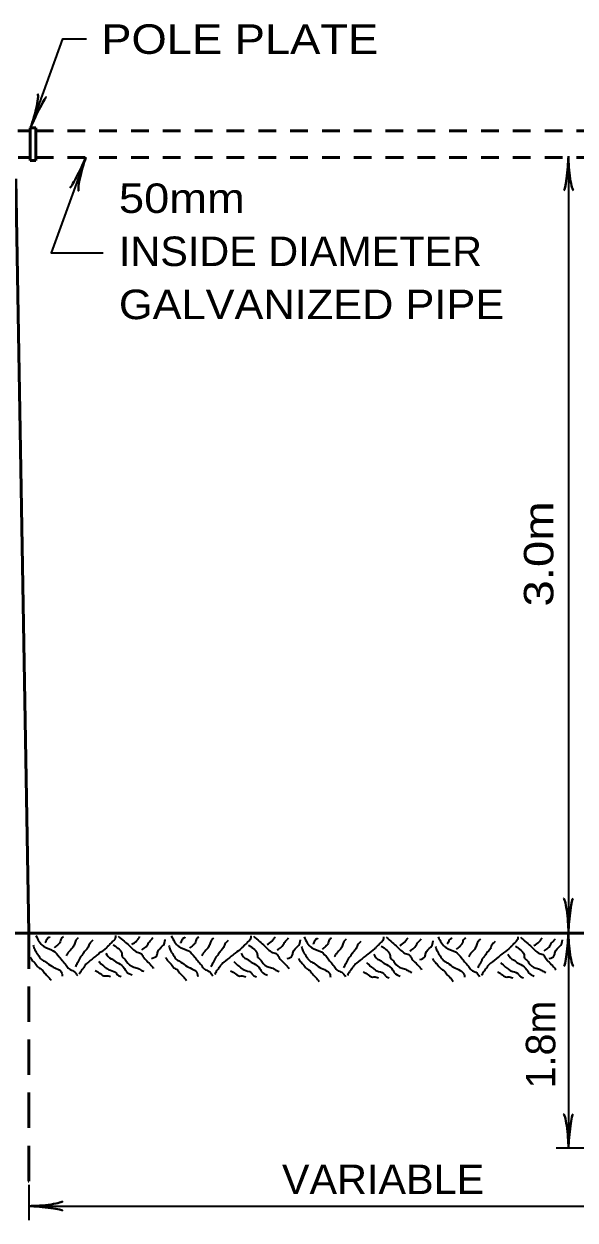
# Model space of a CAD drawing. Extents: x 14808 to 15663, y 10944 to 11488.
# Drawn here: x 15295.9 to 15352, y 11248.2 to 11369.9 of the extents above; entities that cross this region are included whole.
import ezdxf
from ezdxf.enums import TextEntityAlignment as Align

# ---------------------------------------------------------------- set-up
doc = ezdxf.new("R2010")
doc.units = 0
doc.header["$LTSCALE"] = 1.2
doc.linetypes.add('MEDIUM_DASHED', pattern=[4.5, 3, -1.5])
doc.linetypes.add('SHORT_DASHED', pattern=[2.7, 1.5, -1.2])
doc.layers.add('1', color=7, linetype='Continuous', lineweight=53)

msp = doc.modelspace()

# ---------------------------------------------------------------- linework, layer by layer
at = {"layer": '1'}
for p, q in [((15295.278, 11358.975), (15296.525, 11358.975)), ((15296.525, 11359.275), (15296.525, 11355.976)), ((15296.525, 11359.275), (15297.125, 11359.275)), ((15297.125, 11359.275), (15297.125, 11355.976)), ((15295.325, 11356.276), (15296.525, 11356.276)), ((15296.525, 11355.976), (15297.125, 11355.976)), ((15295.063, 11354.093), (15296.402, 11277.361)), ((15267.529, 11277.361), (15491.726, 11277.361))]:
    msp.add_line(p, q, dxfattribs=at)
at = {"layer": '1', "linetype": 'SHORT_DASHED'}
for p, q in [((15297.1, 11358.975), (15369.889, 11358.975)), ((15297.101, 11356.276), (15369.889, 11356.276))]:
    msp.add_line(p, q, dxfattribs=at)
at = {"layer": '1', "linetype": 'MEDIUM_DASHED'}
for p in [(15296.402, 11277.361), (15285.529, 11252.161)]:
    msp.add_line(p, (15296.402, 11252.161), dxfattribs=at)
at = {"layer": '1', "lineweight": 35}
for p, q in [((15373.088, 11255.52), (15350.104, 11255.52)), ((15296.404, 11251.793), (15296.404, 11248.194)), ((15296.404, 11249.616), (15373.132, 11249.616))]:
    msp.add_line(p, q, dxfattribs=at)
for points in [[(15296.595, 11359.332), (15299.878, 11368.353), (15302.278, 11368.353)], [(15302.201, 11356.276), (15298.672, 11346.579), (15303.978, 11346.579)], [(15351.358, 11356.377), (15351.358, 11277.463), (15351.358, 11255.52)]]:
    msp.add_lwpolyline(points, dxfattribs=at)
at = {"layer": '1', "lineweight": 40}
for centre, major_axis, ratio, start_param, end_param in [((15296.731, 11360.676), (-0.557, -2.078), 0.122415, 0.8963533, 3.1415927), ((15297.293, 11360.508), (0.919, 1.909), 0.07063, 6.2823074, 8.5597026), ((15301.502, 11355.099), (0.919, 1.909), 0.07063, 3.1407148, 5.41811), ((15302.065, 11354.932), (0.557, 2.078), 0.122415, 0.8963533, 3.1415927), ((15351.104, 11355.033), (-0.211, -2.108), 0.07063, 6.2823074, 8.5597026), ((15351.689, 11355.068), (-0.187, 2.143), 0.122415, 0.8963533, 3.1415927), ((15351.026, 11278.772), (0.187, -2.143), 0.122415, 0.8963533, 3.1415927), ((15351.611, 11278.807), (0.211, 2.108), 0.07063, 6.2823074, 8.5597026), ((15351.104, 11276.118), (-0.211, -2.108), 0.07063, 6.2823074, 8.5597026), ((15351.104, 11276.118), (-0.211, -2.108), 0.07063, 6.2823074, 8.5597026), ((15351.689, 11276.153), (-0.187, 2.143), 0.122415, 0.8963533, 3.1415927), ((15351.689, 11276.153), (-0.187, 2.143), 0.122415, 0.8963533, 3.1415927), ((15351.026, 11256.83), (0.187, -2.143), 0.122415, 0.8963533, 3.1415927), ((15351.611, 11256.865), (0.211, 2.108), 0.07063, 6.2823074, 8.5597026), ((15297.714, 11249.947), (-2.143, -0.187), 0.122415, 0.8963533, 3.1415927), ((15297.749, 11249.362), (2.108, -0.211), 0.07063, 6.2823074, 8.5597026)]:
    msp.add_ellipse(centre, major_axis=major_axis, ratio=ratio, start_param=start_param, end_param=end_param, dxfattribs=at)
at = {"layer": '1', "lineweight": 35}
for points in [[(15297.127, 11277.125), (15297.895, 11276.05), (15298.893, 11275.589), (15299.507, 11274.975), (15299.814, 11274.591), (15300.198, 11274.131), (15300.505, 11273.747), (15300.966, 11273.516), (15301.349, 11273.056)], [(15298.509, 11277.039), (15298.394, 11276.885), (15298.355, 11276.885), (15298.278, 11276.808), (15298.086, 11276.463), (15298.048, 11276.386)], [(15299.929, 11277), (15299.699, 11276.808), (15299.622, 11276.616), (15299.545, 11276.386), (15299.392, 11276.233), (15299.315, 11276.156), (15298.969, 11275.887)], [(15301.426, 11276.885), (15301.196, 11276.655), (15301.042, 11276.271), (15300.85, 11275.887), (15300.428, 11275.427), (15300.275, 11275.196), (15300.198, 11275.081)], [(15305.226, 11277.125), (15305.226, 11276.971), (15305.15, 11276.741), (15304.996, 11276.587), (15304.843, 11276.434), (15304.535, 11276.127), (15304.305, 11275.896), (15303.614, 11275.359), (15303.23, 11275.052), (15302.463, 11274.438), (15302.155, 11274.131), (15302.002, 11273.9), (15301.772, 11273.593), (15301.541, 11273.209)], [(15305.495, 11277.086), (15306.109, 11276.549), (15306.647, 11276.088), (15307.568, 11275.397), (15307.798, 11275.32), (15308.029, 11275.013), (15308.413, 11274.553), (15308.873, 11274.092), (15309.104, 11273.785)], [(15306.877, 11276.233), (15307.415, 11276.616), (15307.53, 11276.77), (15307.722, 11277.039)], [(15307.914, 11275.695), (15308.336, 11276.002), (15308.605, 11276.386), (15308.681, 11276.501), (15308.835, 11276.655), (15309.065, 11276.924)], [(15308.912, 11274.812), (15309.449, 11275.119), (15309.526, 11275.465), (15310.025, 11276.079), (15310.178, 11276.271), (15310.255, 11276.578), (15310.294, 11276.732)], [(15310.913, 11277.1), (15311.681, 11276.025), (15312.679, 11275.565), (15313.293, 11274.95), (15313.6, 11274.566), (15313.984, 11274.106), (15314.291, 11273.722), (15314.752, 11273.492), (15315.136, 11273.031)], [(15312.295, 11277.014), (15312.18, 11276.86), (15312.142, 11276.86), (15312.065, 11276.784), (15311.873, 11276.438), (15311.835, 11276.361)], [(15313.715, 11276.976), (15313.485, 11276.784), (15313.408, 11276.592), (15313.332, 11276.361), (15313.178, 11276.208), (15313.101, 11276.131), (15312.756, 11275.862)], [(15315.213, 11276.861), (15314.982, 11276.63), (15314.829, 11276.246), (15314.637, 11275.862), (15314.214, 11275.402), (15314.061, 11275.171), (15313.984, 11275.056)], [(15319.013, 11277.1), (15319.013, 11276.947), (15318.936, 11276.716), (15318.783, 11276.563), (15318.629, 11276.409), (15318.322, 11276.102), (15318.092, 11275.872), (15317.401, 11275.334), (15317.017, 11275.027), (15316.249, 11274.413), (15315.942, 11274.106), (15315.788, 11273.876), (15315.558, 11273.568), (15315.328, 11273.185)], [(15319.282, 11277.062), (15319.896, 11276.524), (15320.433, 11276.064), (15321.354, 11275.373), (15321.585, 11275.296), (15321.815, 11274.989), (15322.199, 11274.528), (15322.66, 11274.067), (15322.89, 11273.76)], [(15320.664, 11276.208), (15321.201, 11276.592), (15321.316, 11276.745), (15321.508, 11277.014)], [(15321.7, 11275.67), (15322.122, 11275.978), (15322.391, 11276.361), (15322.468, 11276.477), (15322.621, 11276.63), (15322.852, 11276.899)], [(15324.427, 11277.001), (15325.195, 11275.926), (15326.193, 11275.466), (15326.807, 11274.851), (15327.114, 11274.467), (15327.498, 11274.007), (15327.805, 11273.623), (15328.266, 11273.393), (15328.65, 11272.932)], [(15325.809, 11276.915), (15325.694, 11276.761), (15325.656, 11276.761), (15325.579, 11276.685), (15325.387, 11276.339), (15325.349, 11276.262)], [(15327.23, 11276.877), (15326.999, 11276.685), (15326.922, 11276.493), (15326.846, 11276.262), (15326.692, 11276.109), (15326.615, 11276.032), (15326.27, 11275.763)], [(15328.727, 11276.762), (15328.496, 11276.531), (15328.343, 11276.147), (15328.151, 11275.763), (15327.729, 11275.303), (15327.575, 11275.072), (15327.498, 11274.957)], [(15332.527, 11277.001), (15332.527, 11276.847), (15332.45, 11276.617), (15332.297, 11276.464), (15332.143, 11276.31), (15331.836, 11276.003), (15331.606, 11275.773), (15330.915, 11275.235), (15330.531, 11274.928), (15329.763, 11274.314), (15329.456, 11274.007), (15329.302, 11273.776), (15329.072, 11273.469), (15328.842, 11273.086)], [(15332.796, 11276.963), (15333.41, 11276.425), (15333.947, 11275.965), (15334.869, 11275.274), (15335.099, 11275.197), (15335.329, 11274.89), (15335.713, 11274.429), (15336.174, 11273.968), (15336.404, 11273.661)], [(15334.178, 11276.109), (15334.715, 11276.493), (15334.83, 11276.646), (15335.022, 11276.915)], [(15335.214, 11275.571), (15335.636, 11275.879), (15335.905, 11276.262), (15335.982, 11276.378), (15336.135, 11276.531), (15336.366, 11276.8)], [(15338.09, 11277.001), (15338.858, 11275.926), (15339.856, 11275.466), (15340.47, 11274.851), (15340.777, 11274.467), (15341.161, 11274.007), (15341.468, 11273.623), (15341.929, 11273.393), (15342.313, 11272.932)], [(15339.472, 11276.915), (15339.357, 11276.761), (15339.318, 11276.761), (15339.242, 11276.685), (15339.05, 11276.339), (15339.011, 11276.262)], [(15340.892, 11276.877), (15340.662, 11276.685), (15340.585, 11276.493), (15340.508, 11276.262), (15340.355, 11276.109), (15340.278, 11276.032), (15339.933, 11275.763)], [(15342.389, 11276.762), (15342.159, 11276.531), (15342.005, 11276.147), (15341.814, 11275.763), (15341.391, 11275.303), (15341.238, 11275.072), (15341.161, 11274.957)], [(15346.19, 11277.001), (15346.19, 11276.847), (15346.113, 11276.617), (15345.959, 11276.464), (15345.806, 11276.31), (15345.499, 11276.003), (15345.268, 11275.773), (15344.577, 11275.235), (15344.194, 11274.928), (15343.426, 11274.314), (15343.119, 11274.007), (15342.965, 11273.776), (15342.735, 11273.469), (15342.505, 11273.086)], [(15346.458, 11276.963), (15347.073, 11276.425), (15347.61, 11275.965), (15348.531, 11275.274), (15348.762, 11275.197), (15348.992, 11274.89), (15349.376, 11274.429), (15349.836, 11273.968), (15350.067, 11273.661)], [(15347.84, 11276.109), (15348.378, 11276.493), (15348.493, 11276.646), (15348.685, 11276.915)], [(15348.877, 11275.571), (15349.299, 11275.879), (15349.568, 11276.262), (15349.644, 11276.378), (15349.798, 11276.531), (15350.028, 11276.8)], [(15296.858, 11276.156), (15297.012, 11275.695), (15297.319, 11275.196), (15297.703, 11274.697), (15298.086, 11274.467), (15298.739, 11274.006), (15299.776, 11273.315), (15299.814, 11273.008)], [(15302.923, 11276.655), (15302.578, 11276.271), (15302.386, 11275.849), (15302.079, 11275.503), (15301.848, 11275.158), (15301.618, 11274.889), (15301.503, 11274.62), (15301.349, 11274.352), (15301.157, 11273.968)], [(15304.996, 11276.194), (15305.226, 11276.041), (15305.457, 11275.849), (15305.879, 11275.311), (15305.917, 11274.966), (15306.225, 11274.697), (15306.34, 11274.505), (15307.107, 11273.929), (15307.568, 11273.776), (15307.683, 11273.699), (15308.105, 11273.507)], [(15310.645, 11276.131), (15310.798, 11275.67), (15311.105, 11275.171), (15311.489, 11274.672), (15311.873, 11274.442), (15312.525, 11273.981), (15313.562, 11273.29), (15313.6, 11272.983)], [(15316.71, 11276.63), (15316.364, 11276.246), (15316.172, 11275.824), (15315.865, 11275.478), (15315.635, 11275.133), (15315.404, 11274.864), (15315.289, 11274.596), (15315.136, 11274.327), (15314.944, 11273.943)], [(15318.783, 11276.169), (15319.013, 11276.016), (15319.243, 11275.824), (15319.665, 11275.287), (15319.704, 11274.941), (15320.011, 11274.672), (15320.126, 11274.48), (15320.894, 11273.905), (15321.354, 11273.751), (15321.47, 11273.674), (15321.892, 11273.482)], [(15322.698, 11274.788), (15323.235, 11275.095), (15323.312, 11275.44), (15323.811, 11276.054), (15323.965, 11276.246), (15324.042, 11276.553), (15324.08, 11276.707)], [(15324.159, 11276.032), (15324.312, 11275.571), (15324.619, 11275.072), (15325.003, 11274.573), (15325.387, 11274.343), (15326.04, 11273.882), (15327.076, 11273.191), (15327.114, 11272.884)], [(15330.224, 11276.531), (15329.878, 11276.147), (15329.686, 11275.725), (15329.379, 11275.379), (15329.149, 11275.034), (15328.919, 11274.765), (15328.803, 11274.497), (15328.65, 11274.228), (15328.458, 11273.844)], [(15332.297, 11276.07), (15332.527, 11275.917), (15332.757, 11275.725), (15333.18, 11275.188), (15333.218, 11274.842), (15333.525, 11274.573), (15333.64, 11274.381), (15334.408, 11273.806), (15334.869, 11273.652), (15334.984, 11273.575), (15335.406, 11273.383)], [(15336.212, 11274.689), (15336.749, 11274.996), (15336.826, 11275.341), (15337.325, 11275.955), (15337.479, 11276.147), (15337.556, 11276.454), (15337.594, 11276.608)], [(15337.821, 11276.032), (15337.975, 11275.571), (15338.282, 11275.072), (15338.666, 11274.573), (15339.05, 11274.343), (15339.702, 11273.882), (15340.739, 11273.191), (15340.777, 11272.884)], [(15343.886, 11276.531), (15343.541, 11276.147), (15343.349, 11275.725), (15343.042, 11275.379), (15342.812, 11275.034), (15342.581, 11274.765), (15342.466, 11274.497), (15342.312, 11274.228), (15342.121, 11273.844)], [(15345.959, 11276.07), (15346.19, 11275.917), (15346.42, 11275.725), (15346.842, 11275.188), (15346.881, 11274.842), (15347.188, 11274.573), (15347.303, 11274.381), (15348.071, 11273.806), (15348.531, 11273.652), (15348.646, 11273.575), (15349.069, 11273.383)], [(15349.38, 11274.788), (15349.917, 11275.095), (15349.994, 11275.44), (15350.493, 11276.054), (15350.647, 11276.246), (15350.723, 11276.553), (15350.762, 11276.707)], [(15296.551, 11274.927), (15296.704, 11274.659), (15297.012, 11274.352), (15297.396, 11273.891), (15297.741, 11273.661), (15298.048, 11273.277), (15298.355, 11272.97), (15298.662, 11272.586)], [(15303.499, 11274.505), (15303.998, 11274.044), (15304.19, 11273.891), (15304.535, 11273.661), (15305.226, 11273.392), (15305.457, 11273.123), (15305.802, 11272.97)], [(15304.228, 11275.35), (15304.804, 11274.774), (15304.919, 11274.735), (15305.035, 11274.62), (15305.534, 11274.313), (15306.148, 11273.776), (15306.34, 11273.469), (15306.915, 11273.123)], [(15310.337, 11274.903), (15310.491, 11274.634), (15310.798, 11274.327), (15311.182, 11273.866), (15311.527, 11273.636), (15311.835, 11273.252), (15312.142, 11272.945), (15312.449, 11272.561)], [(15317.285, 11274.48), (15317.784, 11274.02), (15317.976, 11273.866), (15318.322, 11273.636), (15319.013, 11273.367), (15319.243, 11273.099), (15319.589, 11272.945)], [(15318.015, 11275.325), (15318.591, 11274.749), (15318.706, 11274.711), (15318.821, 11274.596), (15319.32, 11274.289), (15319.934, 11273.751), (15320.126, 11273.444), (15320.702, 11273.099)], [(15323.852, 11274.804), (15324.005, 11274.535), (15324.312, 11274.228), (15324.696, 11273.767), (15325.042, 11273.537), (15325.349, 11273.153), (15325.656, 11272.846), (15325.963, 11272.462)], [(15330.8, 11274.381), (15331.299, 11273.921), (15331.49, 11273.767), (15331.836, 11273.537), (15332.527, 11273.268), (15332.757, 11272.999), (15333.103, 11272.846)], [(15331.529, 11275.226), (15332.105, 11274.65), (15332.22, 11274.612), (15332.335, 11274.497), (15332.834, 11274.19), (15333.448, 11273.652), (15333.64, 11273.345), (15334.216, 11272.999)], [(15337.514, 11274.804), (15337.668, 11274.535), (15337.975, 11274.228), (15338.359, 11273.767), (15338.704, 11273.537), (15339.011, 11273.153), (15339.318, 11272.846), (15339.625, 11272.462)], [(15344.462, 11274.381), (15344.961, 11273.921), (15345.153, 11273.767), (15345.499, 11273.537), (15346.19, 11273.268), (15346.42, 11272.999), (15346.765, 11272.846)], [(15345.192, 11275.226), (15345.767, 11274.65), (15345.883, 11274.612), (15345.998, 11274.497), (15346.497, 11274.19), (15347.111, 11273.652), (15347.303, 11273.345), (15347.879, 11272.999)], [(15303.154, 11273.584), (15303.422, 11273.43), (15303.921, 11273.085), (15303.998, 11273.046), (15304.228, 11273.046), (15304.727, 11272.97)], [(15316.94, 11273.559), (15317.209, 11273.406), (15317.708, 11273.06), (15317.784, 11273.022), (15318.015, 11273.022), (15318.514, 11272.945)], [(15330.454, 11273.46), (15330.723, 11273.307), (15331.222, 11272.961), (15331.299, 11272.923), (15331.529, 11272.923), (15332.028, 11272.846)], [(15344.117, 11273.46), (15344.385, 11273.307), (15344.885, 11272.961), (15344.961, 11272.923), (15345.192, 11272.923), (15345.691, 11272.846)]]:
    msp.add_spline(points, degree=3, dxfattribs=at)

# ---------------------------------------------------------------- texts
at = {"layer": '1'}
for s, width, p in [('POLE PLATE', 1.15, (15303.78, 11366.81)), ('50mm', 1.15, (15305.576, 11350.628)), ('INSIDE DIAMETER', 1.05, (15305.576, 11345.228)), ('GALVANIZED PIPE', 1.1, (15305.576, 11339.828))]:
    msp.add_text(s, height=3, dxfattribs=dict(at, width=width)).set_placement(p)
at = {"layer": '1', "width": 1.2}
msp.add_text('3.0m', height=3, rotation=90, dxfattribs=at).set_placement((15349.818, 11315.948), align=Align.CENTER)
at = {"layer": '1'}
msp.add_text('1.8m', height=3, rotation=90, dxfattribs=at).set_placement((15350.016, 11266.049), align=Align.CENTER)
at = {"layer": '1', "width": 1.05}
msp.add_text('VARIABLE', height=3, dxfattribs=at).set_placement((15332.477, 11250.837), align=Align.CENTER)

doc.saveas('drawing.dxf')
